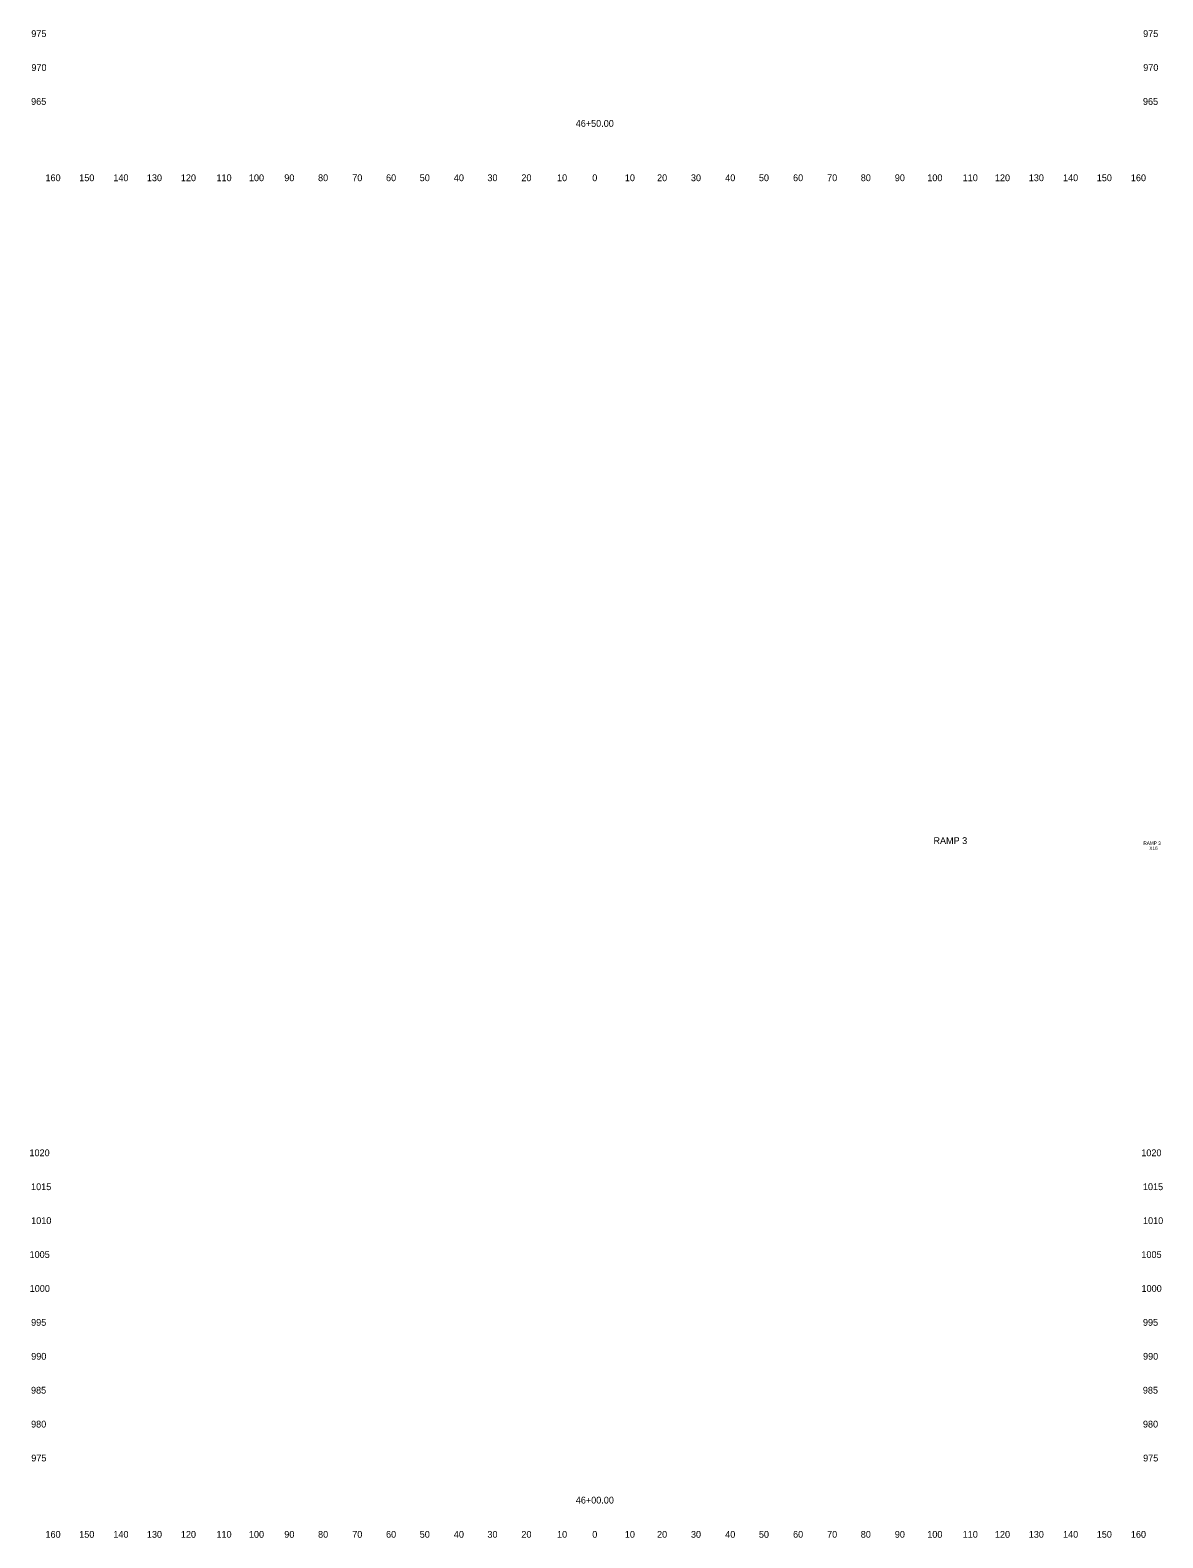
# Model space of a CAD drawing. Extents: x 4994 to 5843, y 4997 to 8804.
# Drawn here: x 5508.6 to 5842.5, y 6997.5 to 7442 of the extents above; entities that cross this region are included whole.
import ezdxf

# ---------------------------------------------------------------- set-up
doc = ezdxf.new("R2010")
doc.units = 0
for name, color, linetype in [('RD_SHT_ID', 7, 'Continuous'), ('RD_XS_TX_Offset', 7, 'Continuous'), ('RD_XS_TX_Station', 7, 'Continuous')]:
    doc.layers.add(name, color=color, linetype=linetype)

msp = doc.modelspace()

# ---------------------------------------------------------------- texts
at = {"layer": 'RD_SHT_ID'}
for s, height, p in [('RAMP 3', 2, (5774.89, 7202.06)), ('RAMP 3', 1, (5836.78, 7201.8)), ('X16', 1, (5838.55, 7200.3))]:
    msp.add_text(s, height=height, dxfattribs=at).set_placement(p)
at = {"layer": 'RD_XS_TX_Offset'}
for s, p in [('975', (5508.91, 7440)), ('975', (5836.71, 7440)), ('970', (5508.94, 7430)), ('970', (5836.74, 7430)), ('965', (5508.86, 7420)), ('965', (5836.66, 7420)), ('160', (5513.1, 7397.5)), ('150', (5523.04, 7397.5)), ('140', (5533.1, 7397.5)), ('130', (5542.99, 7397.5)), ('120', (5553.01, 7397.5)), ('110', (5563.51, 7397.5)), ('100', (5573.07, 7397.5)), ('90', (5583.5, 7397.5)), ('80', (5593.46, 7397.5)), ('70', (5603.54, 7397.5)), ('60', (5613.5, 7397.5)), ('50', (5623.43, 7397.5)), ('40', (5633.5, 7397.5)), ('30', (5643.39, 7397.5)), ('20', (5653.4, 7397.5)), ('10', (5663.91, 7397.5)), ('0', (5674.3, 7397.5)), ('0', (5674.3, 7397.5)), ('10', (5683.91, 7397.5)), ('20', (5693.4, 7397.5)), ('30', (5703.39, 7397.5)), ('40', (5713.5, 7397.5)), ('50', (5723.43, 7397.5)), ('60', (5733.5, 7397.5)), ('70', (5743.54, 7397.5)), ('80', (5753.46, 7397.5)), ('90', (5763.5, 7397.5)), ('100', (5773.07, 7397.5)), ('110', (5783.51, 7397.5)), ('120', (5793.01, 7397.5)), ('130', (5802.99, 7397.5)), ('140', (5813.1, 7397.5)), ('150', (5823.04, 7397.5)), ('160', (5833.1, 7397.5)), ('1020', (5508.37, 7110)), ('1020', (5836.17, 7110)), ('1015', (5508.85, 7100)), ('1015', (5836.65, 7100)), ('1010', (5508.88, 7090)), ('1010', (5836.68, 7090)), ('1005', (5508.4, 7080)), ('1005', (5836.2, 7080)), ('1000', (5508.44, 7070)), ('1000', (5836.24, 7070)), ('995', (5508.86, 7060)), ('995', (5836.66, 7060)), ('990', (5508.89, 7050)), ('990', (5836.69, 7050)), ('985', (5508.83, 7040)), ('985', (5836.63, 7040)), ('980', (5508.86, 7030)), ('980', (5836.66, 7030)), ('975', (5508.91, 7020)), ('975', (5836.71, 7020)), ('160', (5513.1, 6997.5)), ('150', (5523.04, 6997.5)), ('140', (5533.1, 6997.5)), ('130', (5542.99, 6997.5)), ('120', (5553.01, 6997.5)), ('110', (5563.51, 6997.5)), ('100', (5573.07, 6997.5)), ('90', (5583.5, 6997.5)), ('80', (5593.46, 6997.5)), ('70', (5603.54, 6997.5)), ('60', (5613.5, 6997.5)), ('50', (5623.43, 6997.5)), ('40', (5633.5, 6997.5)), ('30', (5643.39, 6997.5)), ('20', (5653.4, 6997.5)), ('10', (5663.91, 6997.5)), ('0', (5674.3, 6997.5)), ('0', (5674.3, 6997.5)), ('10', (5683.91, 6997.5)), ('20', (5693.4, 6997.5)), ('30', (5703.39, 6997.5)), ('40', (5713.5, 6997.5)), ('50', (5723.43, 6997.5)), ('60', (5733.5, 6997.5)), ('70', (5743.54, 6997.5)), ('80', (5753.46, 6997.5)), ('90', (5763.5, 6997.5)), ('100', (5773.07, 6997.5)), ('110', (5783.51, 6997.5)), ('120', (5793.01, 6997.5)), ('130', (5802.99, 6997.5)), ('140', (5813.1, 6997.5)), ('150', (5823.04, 6997.5)), ('160', (5833.1, 6997.5))]:
    msp.add_text(s, height=2, dxfattribs=at).set_placement(p)
at = {"layer": 'RD_XS_TX_Station'}
for s, p in [('46+50.00', (5669.42, 7413.52)), ('46+00.00', (5669.45, 7007.59))]:
    msp.add_text(s, height=2, dxfattribs=at).set_placement(p)

doc.saveas('drawing.dxf')
